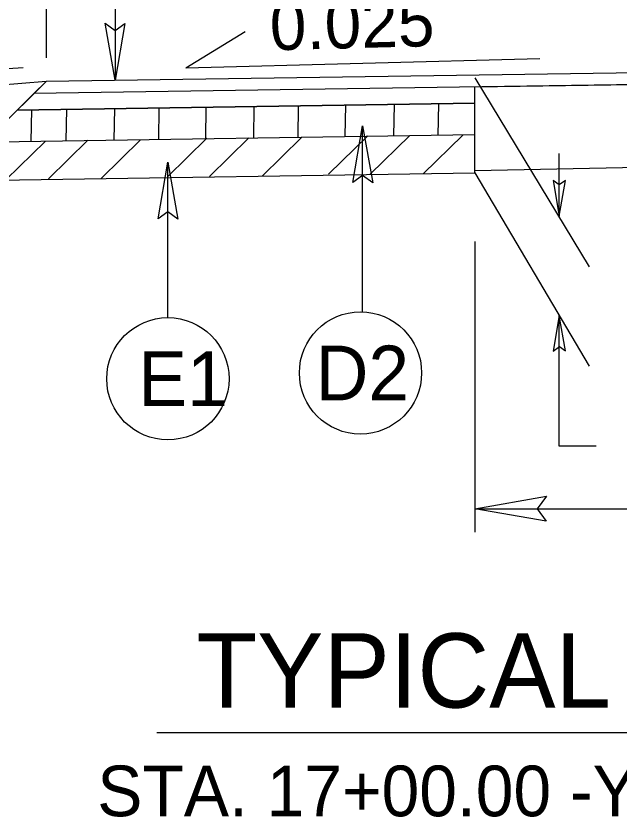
# Model space of a CAD drawing. Extents: x 2176024 to 2177225, y 75947 to 76635.
# Drawn here: x 2176189.73 to 2176202.53, y 76460.53 to 76477.51 of the extents above; entities that cross this region are included whole.
import ezdxf

# ---------------------------------------------------------------- set-up
doc = ezdxf.new("R2010")
doc.units = 0
for name, color, linetype in [('Exist XS Ground Line', 7, 'Continuous'), ('Old_Level_1', 7, 'Continuous'), ('Old_Level_11', 7, 'Continuous'), ('Old_Level_3', 7, 'Continuous'), ('Prop Dimension', 7, 'Continuous'), ('Typical Curb CELL', 7, 'Continuous'), ('Typical Pavement Slope CELL', 7, 'Continuous'), ('Typical Pavement Slope Information CELL', 7, 'Continuous'), ('Typical Shoulder Slope CELL', 7, 'Continuous'), ('Typical Slope Point Local CELL', 7, 'Continuous'), ('Typical Terminator CELL', 7, 'Continuous'), ('Typical Text Label CELL', 7, 'Continuous')]:
    doc.layers.add(name, color=color, linetype=linetype)

msp = doc.modelspace()

# ---------------------------------------------------------------- linework, layer by layer
at = {"layer": 'Exist XS Ground Line'}
msp.add_line((2176199.455, 76474.235), (2176206.375, 76474.378), dxfattribs=at)
at = {"layer": 'Old_Level_1'}
for p, q in [((2176197.739, 76474.973), (2176197.748, 76475.635)), ((2176198.679, 76474.98), (2176198.688, 76475.649)), ((2176190.049, 76474.849), (2176190.059, 76475.521)), ((2176190.793, 76474.862), (2176190.802, 76475.532)), ((2176191.81, 76474.876), (2176191.82, 76475.547)), ((2176192.751, 76474.883), (2176192.761, 76475.561)), ((2176193.748, 76474.907), (2176193.758, 76475.576)), ((2176194.768, 76474.928), (2176194.777, 76475.591)), ((2176195.708, 76474.936), (2176195.718, 76475.605)), ((2176196.706, 76474.96), (2176196.715, 76475.62)), ((2176196.353, 76474.154), (2176197.188, 76474.973)), ((2176197.237, 76474.158), (2176198.073, 76474.977)), ((2176198.356, 76474.162), (2176199.197, 76474.986)), ((2176189.518, 76474.041), (2176190.345, 76474.851)), ((2176190.412, 76474.059), (2176191.247, 76474.878)), ((2176191.531, 76474.063), (2176192.366, 76474.882)), ((2176192.939, 76474.104), (2176193.775, 76474.923)), ((2176193.825, 76474.109), (2176194.661, 76474.928)), ((2176194.944, 76474.113), (2176195.78, 76474.932)), ((2176192.714, 76462.319), (2176220.036, 76462.319))]:
    msp.add_line(p, q, dxfattribs=at)
at = {"layer": 'Old_Level_11'}
for p, q in [((2176191.827, 76480.452), (2176191.827, 76476.149)), ((2176197.075, 76471.237), (2176197.075, 76475.182)), ((2176192.946, 76471.115), (2176192.946, 76474.411))]:
    msp.add_line(p, q, dxfattribs=at)
for points in [[(2176192.034, 76477.349), (2176191.827, 76476.149), (2176191.614, 76477.355), (2176191.827, 76477.202)], [(2176196.868, 76473.982), (2176197.075, 76475.182), (2176197.288, 76473.976), (2176197.075, 76474.129)], [(2176192.739, 76473.211), (2176192.946, 76474.411), (2176193.159, 76473.204), (2176192.946, 76473.357)]]:
    msp.add_lwpolyline(points, close=True, dxfattribs=at)
for centre in [(2176197.029, 76469.942), (2176192.946, 76469.819)]:
    msp.add_circle(centre, 1.296, dxfattribs=at)
at = {"layer": 'Prop Dimension'}
for p, q in [((2176190.375, 76476.625), (2176190.375, 76485.701)), ((2176199.455, 76476.199), (2176201.88, 76472.191)), ((2176201.243, 76473.266), (2176201.243, 76474.594)), ((2176199.455, 76474.184), (2176201.88, 76470.089)), ((2176199.453, 76472.732), (2176199.453, 76466.568)), ((2176201.244, 76468.388), (2176201.244, 76471.164)), ((2176202.024, 76468.388), (2176201.244, 76468.388)), ((2176199.453, 76467.059), (2176223.232, 76467.059))]:
    msp.add_line(p, q, dxfattribs=at)
at = {"layer": 'Typical Curb CELL'}
for p, q in [((2176199.455, 76474.183), (2176199.455, 76476.006)), ((2176179.051, 76473.88), (2176199.455, 76474.183))]:
    msp.add_line(p, q, dxfattribs=at)
at = {"layer": 'Typical Pavement Slope CELL'}
for p, q in [((2176190.362, 76476.121), (2176188.246, 76474.016)), ((2176199.455, 76475.661), (2176189.754, 76475.517)), ((2176199.443, 76474.989), (2176189.069, 76474.835))]:
    msp.add_line(p, q, dxfattribs=at)
at = {"layer": 'Typical Pavement Slope Information CELL'}
for p, q in [((2176193.325, 76476.414), (2176194.582, 76477.184)), ((2176193.325, 76476.414), (2176200.83, 76476.609)), ((2176185.134, 76476.104), (2176189.88, 76476.417))]:
    msp.add_line(p, q, dxfattribs=at)
at = {"layer": 'Typical Shoulder Slope CELL'}
msp.add_line((2176190.362, 76476.121), (2176184.327, 76475.638), dxfattribs=at)
at = {"layer": 'Typical Slope Point Local CELL'}
for p, q in [((2176206.375, 76476.358), (2176190.362, 76476.12)), ((2176205.654, 76476.348), (2176190.362, 76476.121)), ((2176190.362, 76476.121), (2176190.106, 76475.867)), ((2176205.703, 76476.098), (2176190.106, 76475.867)), ((2176190.106, 76475.867), (2176189.754, 76475.517)), ((2176189.754, 76475.517), (2176199.455, 76475.661))]:
    msp.add_line(p, q, dxfattribs=at)
msp.add_lwpolyline([(2176199.455, 76475.661), (2176199.455, 76476.006), (2176205.703, 76476.098)], dxfattribs=at)
at = {"layer": 'Typical Terminator CELL'}
for points in [[(2176201.111, 76474.02), (2176201.243, 76473.266), (2176201.375, 76474.025), (2176201.241, 76473.929)], [(2176201.376, 76470.41), (2176201.244, 76471.164), (2176201.112, 76470.405), (2176201.246, 76470.502)], [(2176200.962, 76466.799), (2176199.453, 76467.059), (2176200.971, 76467.327), (2176200.778, 76467.059)]]:
    msp.add_lwpolyline(points, close=True, dxfattribs=at)

# ---------------------------------------------------------------- texts
at = {"layer": 'Old_Level_11'}
for s, p in [('D2', (2176196.077, 76469.362)), ('E1', (2176192.318, 76469.239))]:
    msp.add_text(s, height=1.16, rotation=0.0003, dxfattribs=at).set_placement(p)
at = {"layer": 'Old_Level_3'}
msp.add_text('TYPICAL SECTION NO.  3', height=1.5766, rotation=0, dxfattribs=at).set_placement((2176193.55, 76462.847))
at = {"layer": 'Typical Pavement Slope Information CELL'}
msp.add_text('0.025', height=1.0429, rotation=1.4932, dxfattribs=at).set_placement((2176195.119, 76476.783))
at = {"layer": 'Typical Text Label CELL'}
msp.add_text('STA. 17+00.00 -Y- TO STA. 23+52.54 -Y-', height=1.0742, dxfattribs=at).set_placement((2176191.448, 76460.544))

doc.saveas('drawing.dxf')
